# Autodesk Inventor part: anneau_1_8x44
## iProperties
Created: 2011-01
Part Number: anneau_1_8x44
Document SubType Name: Modeling
Designer: eric
Density: 1 g/cm^3
Mass: 0.351753 g
Surface Area: 7.81673 cm^2
Volume: 0.351753 cm^3
Author: eric
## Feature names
1. Base1
